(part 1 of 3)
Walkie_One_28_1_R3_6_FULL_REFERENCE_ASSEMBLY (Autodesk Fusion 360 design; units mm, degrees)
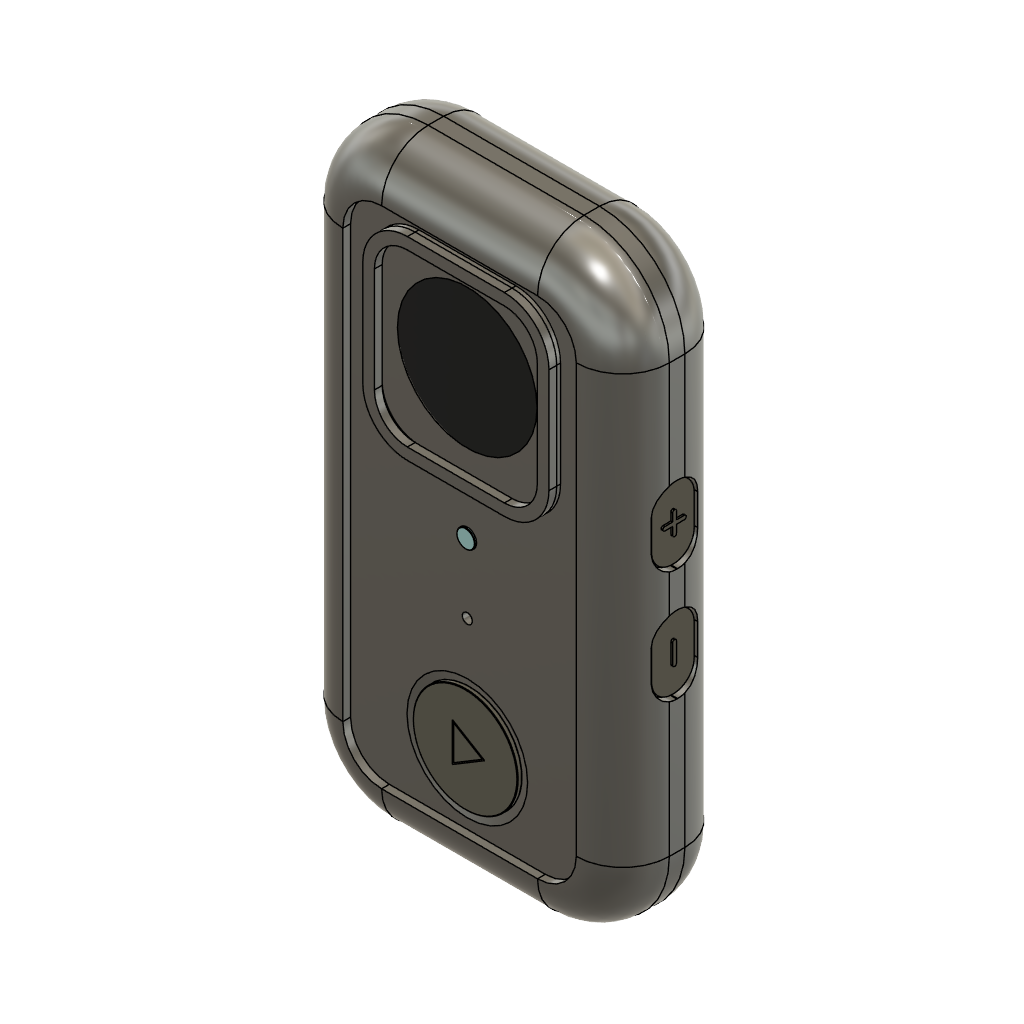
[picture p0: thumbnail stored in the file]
description: Open CASCADE Model
part number: Walkie_One_Concept_27_R2_REFERENCE_ASSEMBLY
description: Part Number
part number: C27_R2_04_Status_Lens
part number: C27_R2_08_Volume_Down_Rigid_Carrier
part number: C27_R2_Microphone_Acoustic_Seal
part number: C27_R2_03_Front_Action_Rigid_Carrier
part number: C27_R2_07_Volume_Up_Rigid_Carrier
part number: C27_R2_Microphone_Acoustic_Membrane
part number: C27_R2_Internal_Right_Angle_Light_Coupler
part number: C27_R2_HW_Closure_33.4_56
part number: C27_R2_HW_Closure_-33.4_56
base_feature "Base Feature1"
base_feature "Base Feature1" bodies "C28_R3_6_P03_One_Piece_Play_Button"
base_feature "Base Feature1" bodies "C28_R3_4_L01_Lens_Fit_Proxy"
base_feature "Base Feature1" bodies "C28_R3_6_P06_One_Piece_Volume_Up"
base_feature "Base Feature1" bodies "C28_R3_6_P07_One_Piece_Volume_Down"
base_feature "Base Feature1" bodies "C28_R3_4_F02_Flexible_Talk_Grip"
base_feature "Base Feature1" bodies "C28_R2_Microphone_BOTTOM_PORT_Offset_Seal_REVIEW"
base_feature "Base Feature1"
base_feature "Base Feature1" bodies "C28_R3_4_L02_Light_Guide_Fit_Proxy"
base_feature "Base Feature1"
base_feature "Base Feature1"
base_feature "Base Feature1"
base_feature "Base Feature1"
base_feature "Base Feature1"
base_feature "Base Feature1"
base_feature "Base Feature1"
base_feature "Base Feature1"
base_feature "Base Feature1"
base_feature "Base Feature1"
base_feature "Base Feature1"
base_feature "Base Feature1" bodies "C28_R1_60_Black_Acoustic_Scrim"
base_feature "Base Feature1"
base_feature "Base Feature1"
base_feature "Base Feature1"
base_feature "Base Feature1"
base_feature "Base Feature1"
base_feature "Base Feature1"
base_feature "Base Feature1"
base_feature "Base Feature1"
base_feature "Base Feature1"
base_feature "Base Feature1"
base_feature "Base Feature1"
base_feature "Base Feature1"
base_feature "Base Feature1"
base_feature "Base Feature1"
base_feature "Base Feature1"
base_feature "Base Feature1"
base_feature "Base Feature1"
base_feature "Base Feature1"
base_feature "Base Feature1"
base_feature "Base Feature1"
base_feature "Base Feature1"
base_feature "Base Feature1"
base_feature "Base Feature1"
base_feature "Base Feature1"
base_feature "Base Feature1"
base_feature "Base Feature1"
base_feature "Base Feature1"
base_feature "Base Feature1" bodies "Nominal U6 envelope - NOT SUPPLIER MODEL"
base_feature "Base Feature1" bodies "Adafruit board XY from Eagle - 0p8 thickness UNVERIFIED", "SPH0645 nominal envelope - bottom acoustic port - internal MEMS omitted", "C2 nominal passive envelope HEIGHT UNVERIFIED", "C4 nominal passive envelope HEIGHT UNVERIFIED", "R1 nominal passive envelope HEIGHT UNVERIFIED", "R2 nominal passive envelope HEIGHT UNVERIFIED"
base_feature "Base Feature1" bodies "C28_R3_REF_PTT_LIDUOLE_NOMINAL_6mm_NOT_OEM_1", "C28_R3_REF_PTT_LIDUOLE_NOMINAL_6mm_NOT_OEM_2", "C28_R3_REF_PTT_LIDUOLE_NOMINAL_6mm_NOT_OEM_3", "C28_R3_REF_PTT_LIDUOLE_NOMINAL_6mm_NOT_OEM_4", "C28_R3_REF_PTT_LIDUOLE_NOMINAL_6mm_NOT_OEM_5", "C28_R3_REF_PTT_LIDUOLE_NOMINAL_6mm_NOT_OEM_6"
place_component sketch "Sketch1"
base_feature "Base Feature1" sketch "Sketch1" bodies "C28_R3_REF_Volume_Up_LIDUOLE_NOMINAL_5mm_NOT_OEM_1", "C28_R3_REF_Volume_Up_LIDUOLE_NOMINAL_5mm_NOT_OEM_2", "C28_R3_REF_Volume_Up_LIDUOLE_NOMINAL_5mm_NOT_OEM_3", "C28_R3_REF_Volume_Up_LIDUOLE_NOMINAL_5mm_NOT_OEM_4", "C28_R3_REF_Volume_Up_LIDUOLE_NOMINAL_5mm_NOT_OEM_5", "C28_R3_REF_Volume_Up_LIDUOLE_NOMINAL_5mm_NOT_OEM_6"
base_feature "Base Feature1" bodies "C28_R3_REF_Volume_Down_LIDUOLE_NOMINAL_5mm_NOT_OEM_1", "C28_R3_REF_Volume_Down_LIDUOLE_NOMINAL_5mm_NOT_OEM_2", "C28_R3_REF_Volume_Down_LIDUOLE_NOMINAL_5mm_NOT_OEM_3", "C28_R3_REF_Volume_Down_LIDUOLE_NOMINAL_5mm_NOT_OEM_4", "C28_R3_REF_Volume_Down_LIDUOLE_NOMINAL_5mm_NOT_OEM_5", "C28_R3_REF_Volume_Down_LIDUOLE_NOMINAL_5mm_NOT_OEM_6"
base_feature "Base Feature1" bodies "C28_R3_REF_Front_LIDUOLE_NOMINAL_12x12x4p3_NOT_OEM_1", "C28_R3_REF_Front_LIDUOLE_NOMINAL_12x12x4p3_NOT_OEM_2", "C28_R3_REF_Front_LIDUOLE_NOMINAL_12x12x4p3_NOT_OEM_3", "C28_R3_REF_Front_LIDUOLE_NOMINAL_12x12x4p3_NOT_OEM_4", "C28_R3_REF_Front_LIDUOLE_NOMINAL_12x12x4p3_NOT_OEM_5", "C28_R3_REF_Front_LIDUOLE_NOMINAL_12x12x4p3_NOT_OEM_6"
base_feature "Base Feature1"
base_feature "Base Feature1"
base_feature "Base Feature1"
base_feature "Base Feature1"
base_feature "Base Feature1"
base_feature "Base Feature1"
base_feature "Base Feature1"
base_feature "Base Feature1"
base_feature "Base Feature1"
base_feature "Base Feature1"
base_feature "Base Feature1"
base_feature "Base Feature1"
base_feature "Base Feature1"
base_feature "Base Feature1"
base_feature "Base Feature1"
base_feature "Base Feature1"
base_feature "Base Feature1"
base_feature "Base Feature1"
base_feature "Base Feature1"
base_feature "Base Feature1"
base_feature "Base Feature1"
base_feature "Base Feature1"
base_feature "Base Feature1"
base_feature "Base Feature1"
base_feature "Base Feature1"
base_feature "Base Feature1"
base_feature "Base Feature1"
base_feature "Base Feature1"
base_feature "Base Feature1"
base_feature "Base Feature1"
base_feature "Base Feature1"
base_feature "Base Feature1"
base_feature "Base Feature1"
base_feature "Base Feature1"
base_feature "Base Feature1"
base_feature "Base Feature1"
base_feature "Base Feature1"
base_feature "Base Feature1"
base_feature "Base Feature1"
base_feature "Base Feature1"
base_feature "Base Feature1"
base_feature "Base Feature1"
base_feature "Base Feature1"
base_feature "Base Feature1"
base_feature "Base Feature1"
base_feature "Base Feature1"
base_feature "Base Feature1"
base_feature "Base Feature1"
base_feature "Base Feature1"
base_feature "Base Feature1"
work_plane "WorkPlane1" AlongDistance -12 ExtraOffset 0
sketch "Sketch1" plane through (0, 0, -12) normal (0, 0, 1) x axis (1, 0, 0)
  line L1 (-40, -75) -> (40, -75)
  line L2 (-40, 75) -> (-40, -75)
  line L3 (40, 75) -> (-40, 75)
  line L4 (40, -75) -> (40, 75)
  line L5 (-40, 75) -> (40, -75)
  line L6 (40, 75) -> (-40, -75)
  point P6 (0, 0)
  point P1 (0, 0)
  point P4 (-40, 75)
  point P5 (40, 75)
  point P3 (-40, -75)
  horizontal L1
  perpendicular L1 L2
  parallel L1 L3
  parallel L2 L4
  coincident L5 P6
  coincident L6 P6
  coincident P1 P6
  dimension "d9" distance P4 P5 = 80
  dimension "d10" distance P3 P4 = 150
extrude "Extrude1" new body sketch "Sketch1" profile of L1 L2 L3 L4 against normal blind 12
fillet "Fillet1" radius 20
fillet "Fillet2" radius 8
sketch "Sketch2" plane through (0, 0, -12) normal (0, 0, 1) x axis (1, 0, 0)
  line L1 (-40, -75) -> (40, -75)
  line L2 (-40, 75) -> (-40, -75)
  line L3 (40, 75) -> (-40, 75)
  line L4 (40, -75) -> (40, 75)
  line L5 (-40, 75) -> (40, -75)
  line L6 (40, 75) -> (-40, -75)
  point P6 (0, 0)
  point P1 (0, 0)
  point P4 (-40, 75)
  point P5 (40, 75)
  point P3 (-40, -75)
  horizontal L1
  perpendicular L1 L2
  parallel L1 L3
  parallel L2 L4
  coincident L5 P6
  coincident L6 P6
  coincident P1 P6
  dimension "d17" distance P4 P5 = 80
  dimension "d18" distance P3 P4 = 150
extrude "Extrude1" new body sketch "Sketch2" profile of L1 L2 L3 L4 along normal blind 12
fillet "Fillet1" radius 20
fillet "Fillet2" radius 8
shell "Shell1" innerThickness 2
shell "Shell1" innerThickness 2
sketch "Sketch3" plane through (38.9, 0, 0) normal (1, 0, 0) x axis (0, 0, -1)
  line L1 (12, -6) -> (9.2, -6)
  circle C1 centre (9.2, -6) radius 1.75
  point P2 (9.2, -6)
  point P3 (9.2, -6)
  coincident P2 P3
  horizontal L1
move "Move1"
position "Position1"
sketch "Sketch4" plane through (-41.9, 0, 0) normal (-1, 0, 0) x axis (0, 0, 1)
  line L1 (-12.1, 39) -> (-11.9, 39)
  line L2 (-18, -9.1) -> (-18, 33.1)
  line L3 (-11.9, -15) -> (-12.1, -15)
  line L4 (-6, 33.1) -> (-6, -9.1)
  line L5 (-12, 12) -> (-12, 17)
  line L6 (-12, 12) -> (-6, 12)
  arc A1 centre (-11.9, 33.1) radius 5.9 clockwise from (-11.9, 39) to (-6, 33.1)
  arc A2 centre (-12.1, 33.1) radius 5.9 clockwise from (-18, 33.1) to (-12.1, 39)
  arc A3 centre (-12.1, -9.1) radius 5.9 clockwise from (-12.1, -15) to (-18, -9.1)
  arc A4 centre (-11.9, -9.1) radius 5.9 clockwise from (-6, -9.1) to (-11.9, -15)
  point P15 (-6, 12)
  parallel L4 L5
  midpoint L4 P15
  perpendicular L5 L6
position "Position2"
sketch "Sketch1" plane through (0, 0, -7.65) normal (0, 0, -1) x axis (-1, 0, 0)
  line L1 (6.0983, 46.8632) -> (5.7178, 36.6947)
  line L2 (-7.7782, 42.5829) -> (6.0983, 46.8632)
  line L3 (5.7178, 36.6947) -> (-7.7782, 42.5829)
  circle C1 centre (0, 42) radius 7.8
  point P3 (6.0983, 46.8632)
  point P2 (5.7178, 36.6947)
  point P4 (-7.7782, 42.5829)
  coincident P3 C1
  coincident P2 C1
  coincident P4 C1
extrude "Extrude1" new body sketch "Sketch1" against normal blind 2
sketch "Sketch5" plane through (0, 0, -7.65) normal (0, 0, -1) x axis (-1, 0, 0)
  circle C1 centre (0, 42) radius 7.8
  circle C2 centre (-0.0119, 65.6304) radius 1.6454
  circle C3 centre (-0.0196, 18.3399) radius 1.6599
  point P3 (-0.0119, 65.6304)
  point P4 (-0.0196, 18.3399)
  dimension "d29" diameter C3 = 3.3197
  dimension "d30" distance P3 P4 = 47.2905
sketch "Sketch2" plane through (0, 0, -2) normal (0, 0, -1) x axis (-1, 0, 0)
  line L1 (20, -67) -> (-20, -67)
  line L2 (32, 55) -> (32, -55)
  line L3 (-20, 67) -> (20, 67)
  line L4 (-32, -55) -> (-32, 55)
  arc A1 centre (-20, -55) radius 12 clockwise from (-20, -67) to (-32, -55)
  arc A2 centre (20, -55) radius 12 clockwise from (32, -55) to (20, -67)
  arc A3 centre (20, 55) radius 12 clockwise from (20, 67) to (32, 55)
  arc A4 centre (-20, 55) radius 12 clockwise from (-32, 55) to (-20, 67)
position "Position3"
sketch "Sketch3" plane through (0, 0, -2) normal (0, 0, -1) x axis (-1, 0, 0)
  line L1 (-5.9719, 65) -> (6, 65)
  line L2 (6, 11) -> (-5.9719, 65)
  line L3 (-5.9719, 63.9971) -> (-6.2719, 65.3)
  line L4 (6.3, 10.7) -> (-1.736, 45.6006)
  line L5 (6, 63.9971) -> (6.3, 65.3)
  line L6 (-6.2719, 10.7) -> (1.7641, 45.6006)
  line L7 (-13.7036, 52.7142) -> (-16.5511, 52.6542)
  line L8 (15.947, 53.3392) -> (13.0996, 53.2792)
  line L9 (-4.773, 16.4076) -> (1.7022, 45.6146)
  line L10 (6, 43) -> (6, 11)
  line L11 (6, 65) -> (6, 53.1295)
  line L12 (16.2667, 23) -> (13.4186, 23)
  line L13 (3.4679, 23) -> (3.3396, 23)
  line L14 (-5.9719, 23) -> (-5.9719, 65)
  line L15 (-5.9719, 11) -> (-5.9719, 12.0029)
  line L16 (-13.3905, 23) -> (-16.2386, 23)
  line L17 (-3.3115, 23) -> (-3.4398, 23)
  arc A1 centre (0.0141, 38) radius 7.7995 clockwise from (-6.2719, 42.6172) to (-6.2719, 33.3828)
  arc A2 centre (0.0141, 38) radius 22.1167 clockwise from (-16.2386, 23) to (-16.5511, 52.6542)
  arc A3 centre (0.0141, 38) radius 22.1167 clockwise from (15.947, 53.3392) to (16.2667, 23)
  arc A4 centre (0.0141, 38) radius 20.1167 clockwise from (13.0996, 53.2792) to (13.4186, 23)
  arc A5 centre (0.0141, 38) radius 20.1167 clockwise from (-13.3905, 23) to (-13.7036, 52.7142)
  point P8 (0.0141, 38)
  point P2 (0.0141, 38)
  point P13 (0.0141, 38)
  point P22 (-5.9719, 63.9971)
  point P23 (6, 63.9971)
  point P26 (-1.736, 45.6006)
  point P27 (1.7022, 45.6146)
  point P28 (1.7641, 45.6006)
  point P30 (6, 43)
  point P35 (3.4679, 23)
  point P36 (-3.3115, 23)
  point P37 (3.3396, 23)
  point P39 (-5.9719, 12.0029)
  point P40 (-3.4398, 23)
  point P16 (0.0141, 38)
  horizontal L1
  perpendicular L1 L14
  parallel L10 L14
  coincident P8 L9
  coincident L2 P8
  coincident P2 P8
  coincident P13 L6
  coincident P13 L4
  horizontal L16
  coincident P22 L14
  collinear L3 L4
  coincident P23 L11
  collinear L5 L6
  coincident A1 P26
  coincident A1 P27
  coincident A1 P28
  coincident A1 P30
  collinear L10 L11
  collinear L12 L13
  coincident L4 P35
  coincident L9 P36
  coincident L2 P37
  collinear L13 L17
  coincident L6 P39
  collinear L14 L15
  collinear L16 L17
  coincident L6 P40
  dimension "d49" distance P16 L17 = 15
extrude "Extrude3" add sketch "Sketch3" profile of A5 A3 L8 L17 along normal blind 2
sketch "Sketch4" plane through (0, 0, -2) normal (0, 0, -1) x axis (-1, 0, 0)
  circle C1 centre (0.0009, 14.35) radius 1.65
  circle C2 centre (-0.001, 61.6494) radius 1.6503
  circle C3 centre (0.0009, 14.35) radius 1.55
  circle C4 centre (-0.001, 61.6494) radius 1.5503
  dimension "d47" = -0.1
  dimension "d48" = -0.1
extrude "Extrude4" add sketch "Sketch4" profile of C3 C4 along normal blind 2
sketch "Sketch5" plane through (0, 0, -2) normal (0, 0, -1) x axis (-1, 0, 0)
  arc A1 centre (0.0141, 38) radius 22.1167 clockwise from (-16.2386, 23) to (-16.5511, 52.6542)
  circle C1 centre (0.0141, 38) radius 18
  concentric A1 C1
  dimension "d53" diameter C1 = 36
extrude "Extrude5" cut sketch "Sketch5" profile of C1 against normal blind 5
sketch "Sketch6" plane through (0, 0, 0) normal (0, 0, 1) x axis (1, 0, 0)
  line L1 (32, 55) -> (32, -55)
  line L2 (-20, 67) -> (20, 67)
  line L3 (-32, -55) -> (-32, 55)
  line L4 (20, -67) -> (-20, -67)
  circle C1 centre (-0.0141, 38) radius 18
  arc A1 centre (20, -55) radius 12 clockwise from (32, -55) to (20, -67)
  arc A2 centre (20, 55) radius 12 clockwise from (20, 67) to (32, 55)
  arc A3 centre (-20, 55) radius 12 clockwise from (-32, 55) to (-20, 67)
  arc A4 centre (-20, -55) radius 12 clockwise from (-20, -67) to (-32, -55)
  circle C2 centre (0, 0) radius 2.4048
  point P1 (0, 0)
  point P15 (0, 0)
  coincident P1 P15
  dimension "d62" diameter C2 = 4.8097 (= "4.7096909154 mm + 0.1 mm")
extrude "Extrude6" cut sketch "Sketch6" profile of C2 against normal blind 1
sketch "Sketch7" plane through (0, 0, 0) normal (0, 0, 1) x axis (1, 0, 0)
  line L1 (32, 55) -> (32, -55)
  line L2 (-20, 67) -> (20, 67)
  line L3 (-32, -55) -> (-32, 55)
  line L4 (20, -67) -> (-20, -67)
  circle C1 centre (-0.0141, 38) radius 18
  arc A1 centre (20, -55) radius 12 clockwise from (32, -55) to (20, -67)
  arc A2 centre (20, 55) radius 12 clockwise from (20, 67) to (32, 55)
  arc A3 centre (-20, 55) radius 12 clockwise from (-32, 55) to (-20, 67)
  arc A4 centre (-20, -55) radius 12 clockwise from (-20, -67) to (-32, -55)
  circle C2 centre (0.0002, -14.0006) radius 1.1009
  circle C3 centre (0.0002, -14.0006) radius 1.3009
  circle C4 centre (0.0002, -18.0006) radius 1.3009
  circle C5 centre (0, 0) radius 2.4048
  dimension "d59" = 0.2
extrude "Extrude7" cut sketch "Sketch7" profile of C4 against normal blind 2
sketch "Sketch8" plane through (0, 0, -2) normal (0, 0, -1) x axis (-1, 0, 0)
position "Position4"
sketch "Sketch9" plane through (0, 0, -2) normal (0, 0, -1) x axis (-1, 0, 0)
position "Position5"
sketch "Sketch10" plane through (0, 0, -2) normal (0, 0, -1) x axis (-1, 0, 0)
  line L1 (-5.715, -10.888) -> (5.715, -10.888)
  line L2 (-8.255, -21.048) -> (-8.255, -13.428)
  line L3 (5.715, -23.588) -> (-5.715, -23.588)
  line L4 (8.255, -13.428) -> (8.255, -21.048)
  line L5 (8.255, -21.048) -> (-8.255, -13.428)
  line L6 (-8.255, -23.588) -> (8.255, -23.588)
  line L7 (-8.255, -10.888) -> (-8.255, -23.588)
  line L8 (8.255, -10.888) -> (-8.255, -10.888)
  line L9 (8.255, -23.588) -> (8.255, -10.888)
  line L10 (-8.255, -10.888) -> (8.255, -23.588)
  line L11 (8.255, -10.888) -> (-8.255, -23.588)
  line L12 (8.455, -10.688) -> (-8.455, -10.688)
  line L13 (8.455, -23.788) -> (8.455, -10.688)
  line L14 (-8.455, -23.788) -> (8.455, -23.788)
  line L15 (-8.455, -10.688) -> (-8.455, -23.788)
  line L16 (-10.455, -25.788) -> (10.455, -25.788)
  line L17 (-10.455, -8.688) -> (-10.455, -25.788)
  line L18 (10.455, -8.688) -> (-10.455, -8.688)
  line L19 (10.455, -25.788) -> (10.455, -8.688)
  point P4 (-8.255, -13.428)
  point P10 (-8.255, -13.428)
  point P8 (8.255, -21.048)
  point P11 (8.255, -21.048)
  point P16 (0, -17.238)
  coincident P4 P10
  coincident P8 P11
  horizontal L6
  perpendicular L6 L7
  parallel L6 L8
  parallel L7 L9
  coincident L10 P16
  coincident L11 P16
  midpoint L5 P16
  dimension "d63" = -0.2
  dimension "d66" = -2
extrude "Extrude9" add sketch "Sketch10" profile of L13 L12 L14 L15 L16 L19 L17 L18 along normal blind 3
sketch "Sketch11" plane through (0, 0, 0) normal (0, 0, 1) x axis (1, 0, 0)
  line L1 (32, 55) -> (32, -55)
  line L2 (-20, 67) -> (20, 67)
  line L3 (-32, -55) -> (-32, 55)
  line L4 (20, -67) -> (-20, -67)
  circle C1 centre (0.0002, -18.0006) radius 1.3009
  circle C2 centre (0, 0) radius 2.4048
  circle C3 centre (-0.0141, 38) radius 18
  arc A1 centre (20, -55) radius 12 clockwise from (32, -55) to (20, -67)
  arc A2 centre (20, 55) radius 12 clockwise from (20, 67) to (32, 55)
  arc A3 centre (-20, 55) radius 12 clockwise from (-32, 55) to (-20, 67)
  arc A4 centre (-20, -55) radius 12 clockwise from (-20, -67) to (-32, -55)
  circle C4 centre (0, -47) radius 13.35
  circle C5 centre (0, -47) radius 13.55
  dimension "d69" = 0.2
extrude "Extrude10" cut sketch "Sketch11" profile of C1 C2 C3 C5 against normal blind 3
combine "Combine1" bodies "C28_R3_4_L02_Light_Guide_Fit_Proxy (1)"
sketch "Sketch1" plane through (-40.6, 0, 0) normal (1, 0, 0) x axis (0, 0, -1)
  line L1 (6, -9.1) -> (6, 33.1)
  line L2 (12.1, -15) -> (11.9, -15)
  line L3 (18, 33.1) -> (18, -9.1)
  line L4 (11.9, 39) -> (12.1, 39)
  line L5 (11.9, 37) -> (12.1, 37)
  line L6 (12.1, -13) -> (11.9, -13)
  line L7 (6, 11) -> (18, 11)
  line L8 (16, -4) -> (16, -9.1)
  line L9 (16, 33.1) -> (16, 26)
  line L10 (8, 26) -> (8, 33.1)
  line L11 (8, -9.1) -> (8, 11)
  line L12 (16, -4) -> (18, -4)
  line L13 (6, -4) -> (8, -4)
  line L14 (16, 26) -> (18, 26)
  line L15 (6, 26) -> (8, 26)
  arc A1 centre (11.9, -9.1) radius 5.9 clockwise from (11.9, -15) to (6, -9.1)
  arc A2 centre (12.1, -9.1) radius 5.9 clockwise from (18, -9.1) to (12.1, -15)
  arc A3 centre (12.1, 33.1) radius 5.9 clockwise from (12.1, 39) to (18, 33.1)
  arc A4 centre (11.9, 33.1) radius 5.9 clockwise from (6, 33.1) to (11.9, 39)
  arc A5 centre (12.1, 33.1) radius 3.9 clockwise from (12.1, 37) to (16, 33.1)
  arc A6 centre (11.9, 33.1) radius 3.9 clockwise from (8, 33.1) to (11.9, 37)
  arc A7 centre (11.9, -9.1) radius 3.9 clockwise from (11.9, -13) to (8, -9.1)
  arc A8 centre (12.1, -9.1) radius 3.9 clockwise from (16, -9.1) to (12.1, -13)
  point P26 (18, 11)
  point P27 (6, 11)
  point P34 (8, 11)
  point P36 (8, -4)
  coincident L3 P26
  coincident L1 P27
  perpendicular L1 L7
  concentric A3 A5
  concentric A4 A6
  concentric A1 A7
  concentric A2 A8
  tangent A5 L5
  tangent A5 L9
  tangent A8 L8
  tangent L5 A6
  tangent A6 L10
  tangent A7 L11
  tangent L6 A8
  tangent A7 L6
  collinear L8 L9
  coincident L7 P34
  collinear L10 L11
  coincident L11 P36
  collinear L12 L13
  collinear L14 L15
  dimension "d75" distance L4 L5 = 2
  dimension "d76" distance L1 L10 = 2
  dimension "d77" distance L2 L6 = 2
  dimension "d78" distance L3 L8 = 2
  dimension "d79" distance L7 L12 = 15
  dimension "d80" distance L7 L14 = 15
extrude "Extrude1" add sketch "Sketch1" profile of L1 A1 L2 A2 L3 A3 L4 A4 L9 L6 A5 L11 L5 A8 A6 A7 L15 L13 along normal blind 3
sketch "Sketch12" plane through (41, 0, 0) normal (1, 0, 0) x axis (0, 0, -1)
  line L1 (6.5, 19) -> (6.5, 27)
  line L2 (12.1, 13.6) -> (11.9, 13.6)
  line L3 (17.5, 27) -> (17.5, 19)
  line L4 (11.9, 32.4) -> (12.1, 32.4)
  line L5 (9.45, 22.5) -> (11.5, 22.5)
  line L6 (9, 23.05) -> (9, 22.95)
  line L7 (11.5, 23.5) -> (9.45, 23.5)
  line L8 (11.5, 25.55) -> (11.5, 23.5)
  line L9 (12.05, 26) -> (11.95, 26)
  line L10 (12.5, 23.5) -> (12.5, 25.55)
  line L11 (14.55, 23.5) -> (12.5, 23.5)
  line L12 (15, 22.95) -> (15, 23.05)
  line L13 (12.5, 22.5) -> (14.55, 22.5)
  line L14 (12.5, 20.45) -> (12.5, 22.5)
  line L15 (11.95, 20) -> (12.05, 20)
  line L16 (11.5, 22.5) -> (11.5, 20.45)
  line L17 (17.6, 27) -> (17.6, 19)
  line L18 (11.9, 32.5) -> (12.1, 32.5)
  line L19 (6.4, 19) -> (6.4, 27)
  line L20 (12.1, 13.5) -> (11.9, 13.5)
  line L21 (6.5, -10) -> (6.5, -2)
  line L22 (12.1, -15.4) -> (11.9, -15.4)
  line L23 (17.5, -2) -> (17.5, -10)
  line L24 (11.9, 3.4) -> (12.1, 3.4)
  line L25 (11.95, -9) -> (12.05, -9)
  line L26 (11.5, -3.45) -> (11.5, -8.55)
  line L27 (12.05, -3) -> (11.95, -3)
  line L28 (12.5, -8.55) -> (12.5, -3.45)
  line L29 (11.9, 3.5) -> (12.1, 3.5)
  line L30 (6.4, -10) -> (6.4, -2)
  line L31 (12.1, -15.5) -> (11.9, -15.5)
  line L32 (17.6, -2) -> (17.6, -10)
  arc A1 centre (11.9, 19) radius 5.4 clockwise from (11.9, 13.6) to (6.5, 19)
  arc A2 centre (12.1, 19) radius 5.4 clockwise from (17.5, 19) to (12.1, 13.6)
  arc A3 centre (12.1, 27) radius 5.4 clockwise from (12.1, 32.4) to (17.5, 27)
  arc A4 centre (11.9, 27) radius 5.4 clockwise from (6.5, 27) to (11.9, 32.4)
  arc A5 centre (9.45, 22.95) radius 0.45 clockwise from (9.45, 22.5) to (9, 22.95)
  arc A6 centre (9.45, 23.05) radius 0.45 clockwise from (9, 23.05) to (9.45, 23.5)
  arc A7 centre (11.95, 25.55) radius 0.45 clockwise from (11.5, 25.55) to (11.95, 26)
  arc A8 centre (12.05, 25.55) radius 0.45 clockwise from (12.05, 26) to (12.5, 25.55)
  arc A9 centre (14.55, 23.05) radius 0.45 clockwise from (14.55, 23.5) to (15, 23.05)
  arc A10 centre (14.55, 22.95) radius 0.45 clockwise from (15, 22.95) to (14.55, 22.5)
  arc A11 centre (12.05, 20.45) radius 0.45 clockwise from (12.5, 20.45) to (12.05, 20)
  arc A12 centre (11.95, 20.45) radius 0.45 clockwise from (11.95, 20) to (11.5, 20.45)
  arc A13 centre (12.1, 19) radius 5.5 clockwise from (17.6, 19) to (12.1, 13.5)
  arc A14 centre (12.1, 27) radius 5.5 clockwise from (12.1, 32.5) to (17.6, 27)
  arc A15 centre (11.9, 27) radius 5.5 clockwise from (6.4, 27) to (11.9, 32.5)
  arc A16 centre (11.9, 19) radius 5.5 clockwise from (11.9, 13.5) to (6.4, 19)
  arc A17 centre (11.9, -10) radius 5.4 clockwise from (11.9, -15.4) to (6.5, -10)
  arc A18 centre (12.1, -10) radius 5.4 clockwise from (17.5, -10) to (12.1, -15.4)
  arc A19 centre (12.1, -2) radius 5.4 clockwise from (12.1, 3.4) to (17.5, -2)
  arc A20 centre (11.9, -2) radius 5.4 clockwise from (6.5, -2) to (11.9, 3.4)
  arc A21 centre (11.95, -8.55) radius 0.45 clockwise from (11.95, -9) to (11.5, -8.55)
  arc A22 centre (11.95, -3.45) radius 0.45 clockwise from (11.5, -3.45) to (11.95, -3)
  arc A23 centre (12.05, -3.45) radius 0.45 clockwise from (12.05, -3) to (12.5, -3.45)
  arc A24 centre (12.05, -8.55) radius 0.45 clockwise from (12.5, -8.55) to (12.05, -9)
  arc A25 centre (12.1, -2) radius 5.5 clockwise from (12.1, 3.5) to (17.6, -2)
  arc A26 centre (11.9, -2) radius 5.5 clockwise from (6.4, -2) to (11.9, 3.5)
  arc A27 centre (11.9, -10) radius 5.5 clockwise from (11.9, -15.5) to (6.4, -10)
  arc A28 centre (12.1, -10) radius 5.5 clockwise from (17.6, -10) to (12.1, -15.5)
  dimension "d83" = 0.1
  dimension "d84" = 0.1
extrude "Extrude11" cut sketch "Sketch12" against normal blind 6.5
sketch "Sketch13" plane through (-41.9, 0, 0) normal (-1, 0, 0) x axis (0, 0, 1)
  line L1 (-12.1, 39) -> (-11.9, 39)
  line L2 (-18, -9.1) -> (-18, 33.1)
  line L3 (-11.9, -15) -> (-12.1, -15)
  line L4 (-6, 33.1) -> (-6, -9.1)
  line L5 (-5.9, 33.1) -> (-5.9, -9.1)
  line L6 (-12.1, 39.1) -> (-11.9, 39.1)
  line L7 (-18.1, -9.1) -> (-18.1, 33.1)
  line L8 (-11.9, -15.1) -> (-12.1, -15.1)
  arc A1 centre (-11.9, 33.1) radius 5.9 clockwise from (-11.9, 39) to (-6, 33.1)
  arc A2 centre (-12.1, 33.1) radius 5.9 clockwise from (-18, 33.1) to (-12.1, 39)
  arc A3 centre (-12.1, -9.1) radius 5.9 clockwise from (-12.1, -15) to (-18, -9.1)
  arc A4 centre (-11.9, -9.1) radius 5.9 clockwise from (-6, -9.1) to (-11.9, -15)
  arc A5 centre (-11.9, -9.1) radius 6 clockwise from (-5.9, -9.1) to (-11.9, -15.1)
  arc A6 centre (-11.9, 33.1) radius 6 clockwise from (-11.9, 39.1) to (-5.9, 33.1)
  arc A7 centre (-12.1, 33.1) radius 6 clockwise from (-18.1, 33.1) to (-12.1, 39.1)
  arc A8 centre (-12.1, -9.1) radius 6 clockwise from (-12.1, -15.1) to (-18.1, -9.1)
  dimension "d87" = 0.1
extrude "Extrude12" cut sketch "Sketch13" against normal blind 6
sketch "Sketch1" plane through (39.3, 0, 0) normal (-1, 0, 0) x axis (0, 0, 1)
  line L1 (-11.9, 13.6) -> (-12.1, 13.6)
  line L2 (-6.5, 27) -> (-6.5, 19)
  line L3 (-12.1, 32.4) -> (-11.9, 32.4)
  line L4 (-17.5, 19) -> (-17.5, 27)
  line L5 (-10.3, 21.8) -> (-8.1, 21.8)
  line L6 (-10.3, 22.65) -> (-10.3, 21.8)
  line L7 (-10.3001, 23.3614) -> (-10.3001, 22.6386)
  line L8 (-10.3, 24.2) -> (-10.3, 23.35)
  line L9 (-8.1, 24.2) -> (-10.3, 24.2)
  line L10 (-8.1, 21.8) -> (-8.1, 24.2)
  line L11 (-17.45, 27.2) -> (-17.45, 18.8)
  line L12 (-15.4, 28.05) -> (-16.6, 28.05)
  line L13 (-14.55, 18.8) -> (-14.55, 27.2)
  line L14 (-16.6, 17.95) -> (-15.4, 17.95)
  line L15 (-6.3821, 31.4759) -> (-21.4932, 31.4759)
  line L16 (-6.3821, 14.6522) -> (-6.3821, 31.4759)
  line L17 (-21.4932, 14.6522) -> (-6.3821, 14.6522)
  line L18 (-21.4932, 31.4759) -> (-21.4932, 14.6522)
  arc A1 centre (-12.1, 19) radius 5.4 clockwise from (-12.1, 13.6) to (-17.5, 19)
  arc A2 centre (-11.9, 19) radius 5.4 clockwise from (-6.5, 19) to (-11.9, 13.6)
  arc A3 centre (-11.9, 27) radius 5.4 clockwise from (-11.9, 32.4) to (-6.5, 27)
  arc A4 centre (-12.1, 27) radius 5.4 clockwise from (-17.5, 27) to (-12.1, 32.4)
  arc A5 centre (-10.95, 22.65) radius 0.65 clockwise from (-10.3, 22.65) to (-10.3001, 22.6386)
  arc A6 centre (-10.95, 23.35) radius 0.65 clockwise from (-10.3001, 23.3614) to (-10.3, 23.35)
  arc A7 centre (-16.6, 27.2) radius 0.85 clockwise from (-17.45, 27.2) to (-16.6, 28.05)
  arc A8 centre (-15.4, 27.2) radius 0.85 clockwise from (-15.4, 28.05) to (-14.55, 27.2)
  arc A9 centre (-15.4, 18.8) radius 0.85 clockwise from (-14.55, 18.8) to (-15.4, 17.95)
  arc A10 centre (-16.6, 18.8) radius 0.85 clockwise from (-16.6, 17.95) to (-17.45, 18.8)
  horizontal L15
  vertical L16
  horizontal L17
  vertical L18
extrude "Extrude1" cut sketch "Sketch1" profile of A1 A2 L2 A3 A4 L4 L5 L6 A5 L7 A6 L8 L9 L10 L11 A7 L12 A8 L13 A9 L14 A10 L15 L17 along normal blind 6
sketch "Sketch1" plane through (39.3, 0, 0) normal (-1, 0, 0) x axis (0, 0, 1)
  line L1 (-11.9, -15.4) -> (-12.1, -15.4)
  line L2 (-6.5, -2) -> (-6.5, -10)
  line L3 (-12.1, 3.4) -> (-11.9, 3.4)
  line L4 (-17.5, -10) -> (-17.5, -2)
  line L5 (-10.3, -7.2) -> (-8.1, -7.2)
  line L6 (-10.3, -6.35) -> (-10.3, -7.2)
  line L7 (-10.3001, -5.6386) -> (-10.3001, -6.3614)
  line L8 (-10.3, -4.8) -> (-10.3, -5.65)
  line L9 (-8.1, -4.8) -> (-10.3, -4.8)
  line L10 (-8.1, -7.2) -> (-8.1, -4.8)
  line L11 (-17.45, -1.8) -> (-17.45, -10.2)
  line L12 (-15.4, -0.95) -> (-16.6, -0.95)
  line L13 (-14.55, -10.2) -> (-14.55, -1.8)
  line L14 (-16.6, -11.05) -> (-15.4, -11.05)
  line L15 (-6.5, 2) -> (-20, 2)
  line L16 (-6.5, -14.8273) -> (-6.5, 2)
  line L17 (-20, -14.8273) -> (-6.5, -14.8273)
  line L18 (-20, 2) -> (-20, -14.8273)
  arc A1 centre (-12.1, -10) radius 5.4 clockwise from (-12.1, -15.4) to (-17.5, -10)
  arc A2 centre (-11.9, -10) radius 5.4 clockwise from (-6.5, -10) to (-11.9, -15.4)
  arc A3 centre (-11.9, -2) radius 5.4 clockwise from (-11.9, 3.4) to (-6.5, -2)
  arc A4 centre (-12.1, -2) radius 5.4 clockwise from (-17.5, -2) to (-12.1, 3.4)
  arc A5 centre (-10.95, -6.35) radius 0.65 clockwise from (-10.3, -6.35) to (-10.3001, -6.3614)
  arc A6 centre (-10.95, -5.65) radius 0.65 clockwise from (-10.3001, -5.6386) to (-10.3, -5.65)
  arc A7 centre (-16.6, -1.8) radius 0.85 clockwise from (-17.45, -1.8) to (-16.6, -0.95)
  arc A8 centre (-15.4, -1.8) radius 0.85 clockwise from (-15.4, -0.95) to (-14.55, -1.8)
  arc A9 centre (-15.4, -10.2) radius 0.85 clockwise from (-14.55, -10.2) to (-15.4, -11.05)
  arc A10 centre (-16.6, -10.2) radius 0.85 clockwise from (-16.6, -11.05) to (-17.45, -10.2)
  horizontal L15
  vertical L16
  horizontal L17
  vertical L18
extrude "Extrude1" cut sketch "Sketch1" profile of A1 A2 L2 A3 A4 L4 L5 L6 A5 L7 A6 L8 L9 L10 L11 A7 L12 A8 L13 A9 L14 A10 L15 L16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 along normal blind 9
sketch "Sketch2" plane through (39.3, 0, 0) normal (-1, 0, 0) x axis (0, 0, 1)
  line L1 (-11.9, -15.4) -> (-12.1, -15.4)
  line L2 (-12.1, 3.4) -> (-11.9, 3.4)
  line L3 (-17.5, -10) -> (-17.5, -2)
  line L4 (-11.9, -13.4) -> (-12.1, -13.4)
  line L5 (-12.1, 1.4) -> (-11.9, 1.4)
  line L6 (-15.5, -2) -> (-17.5, -2)
  line L7 (-6.5, -2) -> (-8.5, -2)
  line L8 (-8.5, -10) -> (-6.5, -10)
  line L9 (-17.5, -10) -> (-15.5, -10)
  arc A1 centre (-12.1, -10) radius 5.4 clockwise from (-12.1, -15.4) to (-17.5, -10)
  arc A2 centre (-11.9, -10) radius 5.4 clockwise from (-6.5, -10) to (-11.9, -15.4)
  arc A3 centre (-11.9, -2) radius 5.4 clockwise from (-11.9, 3.4) to (-6.5, -2)
  arc A4 centre (-12.1, -2) radius 5.4 clockwise from (-17.5, -2) to (-12.1, 3.4)
  arc A5 centre (-12.1, -10) radius 3.4 clockwise from (-12.1, -13.4) to (-15.5, -10)
  arc A6 centre (-11.9, -10) radius 3.4 clockwise from (-8.5, -10) to (-11.9, -13.4)
  arc A7 centre (-11.9, -2) radius 3.4 clockwise from (-11.9, 1.4) to (-8.5, -2)
  arc A8 centre (-12.1, -2) radius 3.4 clockwise from (-15.5, -2) to (-12.1, 1.4)
  point P12 (-17.5, -2)
  point P26 (-17.5, -2)
  point P8 (-6.5, -2)
  point P27 (-6.5, -2)
  point P6 (-6.5, -10)
  point P28 (-6.5, -10)
  point P2 (-17.5, -10)
  point P29 (-17.5, -10)
  coincident P12 P26
  coincident P8 P27
  coincident P6 P28
  coincident P2 P29
  concentric A1 A5
  concentric A2 A6
  concentric A3 A7
  concentric A4 A8
  tangent L4 A6
  tangent A5 L4
  tangent L5 A8
  tangent A7 L5
  collinear L6 L7
  collinear L8 L9
  dimension "d99" distance L1 L4 = 2
  dimension "d101" distance L2 L5 = 2
extrude "Extrude2" add sketch "Sketch2" profile of A1 L1 A2 A3 L2 A4 A8 L5 A5 L4 A6 A7 L7 L9 along normal blind 2
sketch "Sketch2" plane through (39.3, 0, 0) normal (-1, 0, 0) x axis (0, 0, 1)
  line L1 (-11.9, 13.6) -> (-12.1, 13.6)
  line L2 (-6.5, 27) -> (-6.5, 19)
  line L3 (-12.1, 32.4) -> (-11.9, 32.4)
  line L4 (-17.5, 19) -> (-17.5, 27)
  line L5 (-11.9, 15.6) -> (-12.1, 15.6)
  line L6 (-12.1, 30.4) -> (-11.9, 30.4)
  line L7 (-15.5, 27) -> (-17.5, 27)
  line L8 (-6.5, 27) -> (-8.5, 27)
  line L9 (-8.5, 19) -> (-6.5, 19)
  line L10 (-17.5, 19) -> (-15.5, 19)
  arc A1 centre (-12.1, 19) radius 5.4 clockwise from (-12.1, 13.6) to (-17.5, 19)
  arc A2 centre (-11.9, 19) radius 5.4 clockwise from (-6.5, 19) to (-11.9, 13.6)
  arc A3 centre (-11.9, 27) radius 5.4 clockwise from (-11.9, 32.4) to (-6.5, 27)
  arc A4 centre (-12.1, 27) radius 5.4 clockwise from (-17.5, 27) to (-12.1, 32.4)
  arc A5 centre (-12.1, 19) radius 3.4 clockwise from (-12.1, 15.6) to (-15.5, 19)
  arc A6 centre (-11.9, 19) radius 3.4 clockwise from (-8.5, 19) to (-11.9, 15.6)
  arc A7 centre (-11.9, 27) radius 3.4 clockwise from (-11.9, 30.4) to (-8.5, 27)
  arc A8 centre (-12.1, 27) radius 3.4 clockwise from (-15.5, 27) to (-12.1, 30.4)
  point P12 (-17.5, 27)
  point P26 (-17.5, 27)
  point P8 (-6.5, 27)
  point P27 (-6.5, 27)
  point P6 (-6.5, 19)
  point P28 (-6.5, 19)
  point P2 (-17.5, 19)
  point P29 (-17.5, 19)
  coincident P12 P26
  coincident P8 P27
  coincident P6 P28
  coincident P2 P29
  collinear L7 L8
  concentric A1 A5
  concentric A2 A6
  concentric A3 A7
  concentric A4 A8
  tangent A5 L5
  tangent L5 A6
  tangent A7 L6
  tangent L6 A8
  collinear L9 L10
  dimension "d106" distance L1 L5 = 2
  dimension "d108" distance L3 L6 = 2
extrude "Extrude2" add sketch "Sketch2" profile of A1 L1 A2 A3 L3 A4 A6 L5 A5 A7 A8 L6 L8 L10 along normal blind 2
sketch "Sketch3" plane through (37.3, 0, 0) normal (-1, 0, 0) x axis (0, 0, 1)
  line L1 (-6.5, 27) -> (-8.5, 27)
  line L2 (-12.1, 32.4) -> (-11.9, 32.4)
  line L3 (-15.5, 27) -> (-17.5, 27)
  line L4 (-11.9, 30.4) -> (-12.1, 30.4)
  line L5 (-12.1, 34.4) -> (-11.9, 34.4)
  line L6 (-11.9, 28.4) -> (-12.1, 28.4)
  line L7 (-17.5, 27) -> (-15.5, 27)
  line L8 (-6.5, 27) -> (-8.5, 27)
  line L9 (-17.5, 19) -> (-15.5, 19)
  line L10 (-11.9, 13.6) -> (-12.1, 13.6)
  line L11 (-8.5, 19) -> (-6.5, 19)
  line L12 (-12.1, 15.6) -> (-11.9, 15.6)
  line L13 (-12.1, 17.6) -> (-11.9, 17.6)
  line L14 (-11.9, 11.6) -> (-12.1, 11.6)
  line L15 (-17.5, 19) -> (-15.5, 19)
  line L16 (-6.5, 19) -> (-8.5, 19)
  line L17 (-6.6095, 27) -> (-6.6421, 32.2072)
  line L18 (-6.5275, 13.9112) -> (-6.5594, 19)
  line L19 (-17.5, 27) -> (-17.5, 32.0596)
  line L20 (-17.5, 13.9404) -> (-17.5, 19)
  arc A1 centre (-11.9, 27) radius 3.4 clockwise from (-11.9, 30.4) to (-8.5, 27)
  arc A2 centre (-11.9, 27) radius 5.4 clockwise from (-11.9, 32.4) to (-6.5, 27)
  arc A3 centre (-12.1, 27) radius 5.4 clockwise from (-17.5, 27) to (-12.1, 32.4)
  arc A4 centre (-12.1, 27) radius 3.4 clockwise from (-15.5, 27) to (-12.1, 30.4)
  arc A5 centre (-12.1, 27) radius 7.4 clockwise from (-17.5, 32.0596) to (-12.1, 34.4)
  arc A6 centre (-11.9, 27) radius 7.4 clockwise from (-11.9, 34.4) to (-6.6421, 32.2072)
  arc A7 centre (-12.1, 19) radius 3.4 clockwise from (-12.1, 15.6) to (-15.5, 19)
  arc A8 centre (-12.1, 19) radius 5.4 clockwise from (-12.1, 13.6) to (-17.5, 19)
  arc A9 centre (-11.9, 19) radius 5.4 clockwise from (-6.5, 19) to (-11.9, 13.6)
  arc A10 centre (-11.9, 19) radius 3.4 clockwise from (-8.5, 19) to (-11.9, 15.6)
  arc A11 centre (-11.9, 19) radius 7.4 clockwise from (-6.5275, 13.9112) to (-11.9, 11.6)
  arc A12 centre (-12.1, 19) radius 7.4 clockwise from (-12.1, 11.6) to (-17.5, 13.9404)
  point P10 (-15.5, 27)
  point P18 (-15.5, 27)
  point P2 (-8.5, 27)
  point P19 (-8.5, 27)
  point P20 (-15.5, 19)
  point P36 (-15.5, 19)
  point P28 (-8.5, 19)
  point P37 (-8.5, 19)
  point P40 (-6.6095, 27)
  point P41 (-6.5594, 19)
  coincident P10 P18
  perpendicular A4 L7
  coincident P2 P19
  perpendicular A1 L8
  concentric A3 A5
  concentric A2 A6
  tangent L5 A6
  tangent A5 L5
  coincident P20 P36
  perpendicular A7 L15
  coincident P28 P37
  perpendicular A10 L16
  concentric A9 A11
  concentric A8 A12
  tangent A11 L14
  tangent A12 L14
  vertical L19
  coincident L1 P40
  coincident L11 P41
  collinear L17 L18
  collinear L19 L20
  dimension "d114" distance L2 L5 = 2
  dimension "d116" distance L4 L6 = 2
  dimension "d119" distance L12 L13 = 2
  dimension "d121" distance L10 L14 = 2
extrude "Extrude3" add sketch "Sketch3" profile of A1 L1 A2 L2 A3 L3 A4 L4 A5 L5 A6 L7 L8 A7 L9 A8 L10 A9 L11 A10 L12 L14 A11 A12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 along normal blind 1.5
chamfer "Chamfer1" distance 2 distance 0.5
sketch "Sketch3" plane through (37.3, 0, 0) normal (-1, 0, 0) x axis (0, 0, 1)
  line L1 (-17.5, -10) -> (-15.5, -10)
  line L2 (-11.9, -15.4) -> (-12.1, -15.4)
  line L3 (-8.5, -10) -> (-6.5, -10)
  line L4 (-12.1, -13.4) -> (-11.9, -13.4)
  line L5 (-6.5, -2) -> (-8.5, -2)
  line L6 (-12.1, 3.4) -> (-11.9, 3.4)
  line L7 (-15.5, -2) -> (-17.5, -2)
  line L8 (-11.9, 1.4) -> (-12.1, 1.4)
  line L9 (-11.9, -17.4) -> (-12.1, -17.4)
  line L10 (-12.1, -11.4) -> (-11.9, -11.4)
  line L11 (-11.9, -0.6) -> (-12.1, -0.6)
  line L12 (-12.1, 5.4) -> (-11.9, 5.4)
  line L13 (-15.5, -10) -> (-17.5, -10)
  line L14 (-6.5, -10) -> (-8.5, -10)
  line L15 (-8.5, -2) -> (-6.5, -2)
  line L16 (-17.5, -2) -> (-15.5, -2)
  line L17 (-6.5, -2) -> (-6.5, 3.0596)
  line L18 (-6.5, -15.0596) -> (-6.5, -10)
  line L19 (-17.5, -2) -> (-17.5, 3.0596)
  line L20 (-17.5, -15.0596) -> (-17.5, -10)
  arc A1 centre (-12.1, -10) radius 3.4 clockwise from (-12.1, -13.4) to (-15.5, -10)
  arc A2 centre (-12.1, -10) radius 5.4 clockwise from (-12.1, -15.4) to (-17.5, -10)
  arc A3 centre (-11.9, -10) radius 5.4 clockwise from (-6.5, -10) to (-11.9, -15.4)
  arc A4 centre (-11.9, -10) radius 3.4 clockwise from (-8.5, -10) to (-11.9, -13.4)
  arc A5 centre (-11.9, -2) radius 3.4 clockwise from (-11.9, 1.4) to (-8.5, -2)
  arc A6 centre (-11.9, -2) radius 5.4 clockwise from (-11.9, 3.4) to (-6.5, -2)
  arc A7 centre (-12.1, -2) radius 5.4 clockwise from (-17.5, -2) to (-12.1, 3.4)
  arc A8 centre (-12.1, -2) radius 3.4 clockwise from (-15.5, -2) to (-12.1, 1.4)
  arc A9 centre (-11.9, -10) radius 7.4 clockwise from (-6.5, -15.0596) to (-11.9, -17.4)
  arc A10 centre (-12.1, -10) radius 7.4 clockwise from (-12.1, -17.4) to (-17.5, -15.0596)
  arc A11 centre (-12.1, -2) radius 7.4 clockwise from (-17.5, 3.0596) to (-12.1, 5.4)
  arc A12 centre (-11.9, -2) radius 7.4 clockwise from (-11.9, 5.4) to (-6.5, 3.0596)
  parallel L7 L16
  parallel L1 L13
  concentric A3 A9
  concentric A2 A10
  tangent L9 A10
  tangent A9 L9
  collinear L13 L14
  collinear L15 L16
  concentric A7 A11
  concentric A6 A12
  tangent A11 L12
  tangent A12 L12
  perpendicular L7 L19
  vertical L17
  collinear L17 L18
  collinear L19 L20
  dimension "d129" distance L2 L9 = 2
  dimension "d131" distance L4 L10 = 2
  dimension "d133" distance L8 L11 = 2
  dimension "d135" distance L6 L12 = 2
extrude "Extrude3" add sketch "Sketch3" profile of A1 L1 A2 L2 A3 L3 A4 L4 A5 L5 A6 L6 A7 L7 A8 L8 A9 L9 A10 A11 L12 A12 L16 L14 along normal blind 1.5
sketch "Sketch2" plane through (-37.6, 0, 0) normal (1, 0, 0) x axis (0, 0, -1)
  line L1 (8, -4) -> (8, -9.1)
  line L2 (6, -4) -> (8, -4)
  line L3 (6, -9.1) -> (6, -4)
  line L4 (12.1, -15) -> (11.9, -15)
  line L5 (18, -4) -> (18, -9.1)
  line L6 (16, -4) -> (18, -4)
  line L7 (16, -9.1) -> (16, -4)
  line L8 (11.9, -13) -> (12.1, -13)
  line L9 (18, 33.1) -> (18, 26)
  line L10 (11.9, 39) -> (12.1, 39)
  line L11 (6, 26) -> (6, 33.1)
  line L12 (8, 26) -> (6, 26)
  line L13 (8, 33.1) -> (8, 26)
  line L14 (12.1, 37) -> (11.9, 37)
  line L15 (16, 26) -> (16, 33.1)
  line L16 (18, 26) -> (16, 26)
  line L17 (12.1, -17) -> (11.9, -17)
  line L18 (11.9, 41) -> (12.1, 41)
  line L19 (12.1, 35) -> (11.9, 35)
  line L20 (16, -4) -> (18, -4)
  line L21 (6, -4) -> (8, -4)
  line L22 (16, 26) -> (18, 26)
  line L23 (6, 26) -> (8, 26)
  line L24 (18, -14.3536) -> (18, -4)
  line L25 (18, 38.3536) -> (18, 26)
  line L26 (6, -4) -> (6, -14.3536)
  line L27 (6, 38.3536) -> (6, 26)
  arc A1 centre (11.9, -9.1) radius 5.9 clockwise from (11.9, -15) to (6, -9.1)
  arc A2 centre (12.1, -9.1) radius 5.9 clockwise from (18, -9.1) to (12.1, -15)
  arc A3 centre (12.1, -9.1) radius 3.9 clockwise from (16, -9.1) to (12.1, -13)
  arc A4 centre (11.9, -9.1) radius 3.9 clockwise from (11.9, -13) to (8, -9.1)
  arc A5 centre (12.1, 33.1) radius 5.9 clockwise from (12.1, 39) to (18, 33.1)
  arc A6 centre (11.9, 33.1) radius 5.9 clockwise from (6, 33.1) to (11.9, 39)
  arc A7 centre (11.9, 33.1) radius 3.9 clockwise from (8, 33.1) to (11.9, 37)
  arc A8 centre (12.1, 33.1) radius 3.9 clockwise from (12.1, 37) to (16, 33.1)
  arc A9 centre (11.9, -9.1) radius 7.9 clockwise from (11.9, -17) to (6, -14.3536)
  arc A10 centre (12.1, -9.1) radius 7.9 clockwise from (18, -14.3536) to (12.1, -17)
  arc A11 centre (11.9, 33.1) radius 7.9 clockwise from (6, 38.3536) to (11.9, 41)
  arc A12 centre (12.1, 33.1) radius 7.9 clockwise from (12.1, 41) to (18, 38.3536)
  point P16 (18, 26)
  point P40 (18, 26)
  concentric A1 A9
  concentric A2 A10
  tangent A9 L17
  tangent L17 A10
  collinear L20 L21
  concentric A6 A11
  concentric A5 A12
  tangent L18 A12
  tangent L18 A11
  collinear L22 L23
  perpendicular L23 L27
  parallel L5 L24
  coincident P16 P40
  perpendicular L16 L25
  collinear L26 L27
  dimension "d146" distance L4 L17 = 2
  dimension "d148" distance L10 L18 = 2
  dimension "d152" distance L14 L19 = 2
extrude "Extrude2" add sketch "Sketch2" profile of L1 L2 L3 A1 L4 A2 L5 L6 L7 A3 L8 A4 L9 A5 L10 A6 L11 L12 L13 A7 L14 A8 L15 L16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 along normal blind 1.5
sketch "Sketch3" plane through (-40.6, 0, 0) normal (1, 0, 0) x axis (0, 0, -1)
  line L1 (6, 26) -> (8, 26)
  line L2 (6, -4) -> (6, 26)
  line L3 (8, -4) -> (6, -4)
  line L4 (8, -9.1) -> (8, -4)
  line L5 (12.1, -13) -> (11.9, -13)
  line L6 (16, -4) -> (16, -9.1)
  line L7 (18, -4) -> (16, -4)
  line L8 (18, 26) -> (18, -4)
  line L9 (16, 26) -> (18, 26)
  line L10 (16, 33.1) -> (16, 26)
  line L11 (11.9, 37) -> (12.1, 37)
  line L12 (8, 26) -> (8, 33.1)
  arc A1 centre (11.9, -9.1) radius 3.9 clockwise from (11.9, -13) to (8, -9.1)
  arc A2 centre (12.1, -9.1) radius 3.9 clockwise from (16, -9.1) to (12.1, -13)
  arc A3 centre (12.1, 33.1) radius 3.9 clockwise from (12.1, 37) to (16, 33.1)
  arc A4 centre (11.9, 33.1) radius 3.9 clockwise from (8, 33.1) to (11.9, 37)
  circle C1 centre (12, 12) radius 3
extrude "Extrude3" add sketch "Sketch3" profile of C1 along normal blind 0.8
fillet "Fillet1" radius 0.95
sketch "Sketch4" plane through (39.3, 0, 0) normal (-1, 0, 0) x axis (0, 0, 1)
  line L1 (-6.5, -10) -> (-8.5, -10)
  line L2 (-6.5, -2) -> (-6.5, -10)
  line L3 (-8.5, -2) -> (-6.5, -2)
  line L4 (-12.1, 1.4) -> (-11.9, 1.4)
  line L5 (-17.5, -2) -> (-15.5, -2)
  line L6 (-17.5, -10) -> (-17.5, -2)
  line L7 (-15.5, -10) -> (-17.5, -10)
  line L8 (-11.9, -13.4) -> (-12.1, -13.4)
  arc A1 centre (-11.9, -2) radius 3.4 clockwise from (-11.9, 1.4) to (-8.5, -2)
  arc A2 centre (-12.1, -2) radius 3.4 clockwise from (-15.5, -2) to (-12.1, 1.4)
  arc A3 centre (-12.1, -10) radius 3.4 clockwise from (-12.1, -13.4) to (-15.5, -10)
  arc A4 centre (-11.9, -10) radius 3.4 clockwise from (-8.5, -10) to (-11.9, -13.4)
  circle C1 centre (-12, -6) radius 3
  dimension "d174" diameter C1 = 6
extrude "Extrude4" add sketch "Sketch4" profile of C1 along normal blind 0.3
fillet "Fillet1" radius 0.5
sketch "Sketch4" plane through (39.3, 0, 0) normal (-1, 0, 0) x axis (0, 0, 1)
  line L1 (-6.5, 19) -> (-8.5, 19)
  line L2 (-6.5, 27) -> (-6.5, 19)
  line L3 (-8.5, 27) -> (-6.5, 27)
  line L4 (-12.1, 30.4) -> (-11.9, 30.4)
  line L5 (-17.5, 27) -> (-15.5, 27)
  line L6 (-17.5, 19) -> (-17.5, 27)
  line L7 (-15.5, 19) -> (-17.5, 19)
  line L8 (-11.9, 15.6) -> (-12.1, 15.6)
  arc A1 centre (-11.9, 27) radius 3.4 clockwise from (-11.9, 30.4) to (-8.5, 27)
  arc A2 centre (-12.1, 27) radius 3.4 clockwise from (-15.5, 27) to (-12.1, 30.4)
  arc A3 centre (-12.1, 19) radius 3.4 clockwise from (-12.1, 15.6) to (-15.5, 19)
  arc A4 centre (-11.9, 19) radius 3.4 clockwise from (-8.5, 19) to (-11.9, 15.6)
  circle C1 centre (-12, 23) radius 3
  dimension "d169" diameter C1 = 6
extrude "Extrude4" add sketch "Sketch4" profile of C1 along normal blind 0.3
fillet "Fillet1" radius 0.5
sketch "Sketch1" plane through (0, 0, -22) normal (0, 0, 1) x axis (1, 0, 0)
  line L1 (32, 55) -> (32, -55)
  curve K1 (20, 67) -> (32, 55)
  line L2 (-20, 67) -> (20, 67)
  curve K2 (-32, 55) -> (-20, 67)
  line L3 (-32, -55) -> (-32, 55)
  curve K3 (-20, -67) -> (-32, -55)
  line L4 (20, -67) -> (-20, -67)
  curve K4 (32, -55) -> (20, -67)
  line L5 (-16.9755, -50.04) -> (-26.9755, -50.04)
  line L6 (-16.9755, -58.04) -> (-16.9755, -50.04)
  line L7 (-26.9755, -58.04) -> (-16.9755, -58.04)
  line L8 (-26.9755, -50.04) -> (-26.9755, -58.04)
  line L9 (27, -53.04) -> (-27, -53.04)
  line L10 (-27, 26.96) -> (27, 26.96)
  line L11 (27, -53.04) -> (27, 26.96)
  line L12 (57.0368, -13.04) -> (27, -13.04)
  line L13 (0, -53.04) -> (0, 26.96)
  line L14 (0, -13.04) -> (27, -13.04)
  line L15 (26.9755, 23.96) -> (26.9755, 31.96)
  line L16 (16.9755, 23.96) -> (26.9755, 23.96)
  line L17 (16.9755, 31.96) -> (16.9755, 23.96)
  line L18 (26.9755, 31.96) -> (16.9755, 31.96)
  point P16 (27, 26.96)
  point P18 (27, 26.96)
  point P15 (27, -53.04)
  point P19 (27, -53.04)
  point P20 (27, -13.04)
  point P22 (0, 26.96)
  point P23 (0, -53.04)
  point P24 (0, -13.04)
  point P25 (0, -13.04)
  point P12 (-16.9755, -58.04)
  point P13 (-26.9755, -58.04)
  horizontal L5
  vertical L6
  horizontal L7
  vertical L8
  coincident P16 P18
  coincident P15 P19
  midpoint L11 P20
  perpendicular L11 L12
  midpoint L10 P22
  midpoint L9 P23
  midpoint L13 P24
  coincident P24 P25
  dimension "d176" distance P12 P13 = 10
  dimension "d177" distance L5 L9 = 3
  dimension "d178" distance L7 L9 = 5
  dimension "d185" C-Pattern1-Angle = 360
extrude "Extrude3" add sketch "Sketch1" profile of L5 L6 L7 L8 L9 L10 L15 L16 L17 L18 along normal blind 7.6
sketch "Sketch2" plane through (0, 0, -14.4) normal (0, 0, 1) x axis (1, 0, 0)
  line L1 (-16.9755, -58.04) -> (-26.9755, -58.04)
  line L2 (-16.9755, -50.04) -> (-16.9755, -58.04)
  line L3 (-26.9755, -50.04) -> (-16.9755, -50.04)
  line L4 (-26.9755, -58.04) -> (-26.9755, -50.04)
  line L5 (-16.9755, -58.04) -> (-26.9755, -58.04)
  line L6 (-16.9755, -53.34) -> (-16.9755, -58.04)
  line L7 (-26.9755, -53.34) -> (-16.9755, -53.34)
  line L8 (-26.9755, -58.04) -> (-26.9755, -53.34)
  line L9 (27, -53.04) -> (-27, -53.04)
  line L10 (-27, 26.96) -> (27, 26.96)
  line L11 (16.9755, 27.26) -> (26.9755, 27.26)
  line L12 (16.9755, 23.96) -> (16.9755, 31.96)
  line L13 (16.9755, 31.96) -> (26.9755, 31.96)
  line L14 (26.9755, 31.96) -> (26.9755, 23.96)
  point P8 (-16.9755, -53.34)
  point P2 (-26.9755, -58.04)
  point P6 (-26.9755, -58.04)
  point P18 (16.9755, 27.26)
  point P19 (26.9755, 27.26)
  horizontal L5
  vertical L6
  horizontal L7
  vertical L8
  coincident L2 P8
  coincident P2 P6
  horizontal L11
  coincident L12 P18
  coincident L14 P19
  dimension "d181" distance L7 L9 = 0.3
  dimension "d186" distance L10 L11 = 0.3
extrude "Extrude4" add sketch "Sketch2" profile of L1 L2 L4 L5 L6 L7 L8 L11 L12 L13 L14 along normal blind 2
sketch "Sketch3" plane through (0, 0, 1.55) normal (0, 0, 1) x axis (1, 0, 0)
  line L1 (-22, 51) -> (-22, 24)
  line L2 (12.5, 60.5) -> (-12.5, 60.5)
  line L3 (22, 24) -> (22, 51)
  line L4 (-12.5, 14.5) -> (12.5, 14.5)
  line L5 (-12.5, 62.5) -> (12.5, 62.5)
  line L6 (-24, 24) -> (-24, 51)
  line L7 (12.5, 12.5) -> (-12.5, 12.5)
  line L8 (24, 51) -> (24, 24)
  line L9 (27, -53.04) -> (-27, -53.04)
  line L10 (-27, 26.96) -> (27, 26.96)
  line L11 (0, -53.04) -> (0, 26.96)
  line L12 (-55, -13.04) -> (0, -13.04)
  arc A1 centre (-12.5, 24) radius 9.5 clockwise from (-12.5, 14.5) to (-22, 24)
  arc A2 centre (-12.5, 51) radius 9.5 clockwise from (-22, 51) to (-12.5, 60.5)
  arc A3 centre (12.5, 51) radius 9.5 clockwise from (12.5, 60.5) to (22, 51)
  arc A4 centre (12.5, 24) radius 9.5 clockwise from (22, 24) to (12.5, 14.5)
  arc A5 centre (-12.5, 51) radius 11.5 clockwise from (-24, 51) to (-12.5, 62.5)
  arc A6 centre (-12.5, 24) radius 11.5 clockwise from (-12.5, 12.5) to (-24, 24)
  arc A7 centre (12.5, 24) radius 11.5 clockwise from (24, 24) to (12.5, 12.5)
  arc A8 centre (12.5, 51) radius 11.5 clockwise from (12.5, 62.5) to (24, 51)
  point P26 (0, 26.96)
  point P27 (0, -53.04)
  point P28 (0, -13.04)
  midpoint L10 P26
  midpoint L9 P27
  midpoint L11 P28
  perpendicular L11 L12
sketch "Sketch4" plane through (0, 0, -22) normal (0, 0, 1) x axis (1, 0, 0)
  line L1 (26.9755, 31.96) -> (16.9755, 31.96)
  line L2 (26.9755, 23.96) -> (26.9755, 31.96)
  line L3 (16.9755, 23.96) -> (26.9755, 23.96)
  line L4 (16.9755, 31.96) -> (16.9755, 23.96)
  line L5 (-26.9755, -50.04) -> (-26.9755, -58.04)
  line L6 (-16.9755, -50.04) -> (-26.9755, -50.04)
  line L7 (-16.9755, -58.04) -> (-16.9755, -50.04)
  line L8 (-26.9755, -58.04) -> (-16.9755, -58.04)
  line L9 (32, 55) -> (32, -55)
  curve K1 (20, 67) -> (32, 55)
  line L10 (-20, 67) -> (20, 67)
  curve K2 (-32, 55) -> (-20, 67)
  line L11 (-32, -55) -> (-32, 55)
  curve K3 (-20, -67) -> (-32, -55)
  line L12 (20, -67) -> (-20, -67)
  curve K4 (32, -55) -> (20, -67)
  line L13 (38, 3.5) -> (38, 13.5)
  line L14 (22.3952, 8.5) -> (38, 8.5)
  line L15 (38, 6.5) -> (22.6952, 6.5)
  line L16 (22.6952, 10.5) -> (38, 10.5)
  line L17 (22.6952, 6.5) -> (22.6952, 10.5)
  line L18 (38, 8.5) -> (22.6952, 6.5)
  line L19 (22.6952, 10.5) -> (38, 8.5)
  line L20 (38, 6.5) -> (38, 10.5)
  point P20 (38, 8.5)
  point P24 (38, 8.5)
  point P25 (38, 10.5)
  point P26 (38, 6.5)
  point P21 (22.3952, 8.5)
  midpoint L13 P20
  perpendicular L9 L14
  horizontal L15
  parallel L15 L16
  coincident L18 P24
  coincident L19 P24
  coincident P20 P24
  coincident L13 P25
  coincident L13 P26
  vertical L17
  dimension "d187" distance P21 L17 = 0.3
  dimension "d188" distance L14 L16 = 2
  dimension "d189" distance L14 L15 = 2
extrude "Extrude5" add sketch "Sketch4" profile of L9 L15 L16 L17 L20 along normal blind 10
delete_face "DeleteFace1"
sketch "Sketch5" plane through (0, 0, -12) normal (0, 0, 1) x axis (1, 0, 0)
  line L1 (38, 13.5) -> (40, 13.5)
  line L2 (38, 10.5) -> (38, 13.5)
  line L3 (40, 3.5) -> (38, 3.5)
  line L4 (40, 13.5) -> (40, 3.5)
  line L5 (30.3, 12.6508) -> (20.4794, 12.6508)
  line L6 (30.3, 4.5768) -> (30.3, 12.6508)
  line L7 (20.4794, 4.5768) -> (30.3, 4.5768)
  line L8 (20.4794, 12.6508) -> (20.4794, 4.5768)
  line L9 (30, 23.96) -> (30, -50.04)
  line L10 (22.6952, 10.5) -> (38, 10.5)
  line L11 (22.6952, 6.5) -> (22.6952, 10.5)
  line L12 (38, 6.5) -> (22.6952, 6.5)
  line L13 (38, 3.5) -> (38, 6.5)
  horizontal L5
  vertical L6
  horizontal L7
  vertical L8
  dimension "d192" distance L6 L9 = 0.3
extrude "Extrude6" cut sketch "Sketch5" profile of L6 L9 against normal blind 2.3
